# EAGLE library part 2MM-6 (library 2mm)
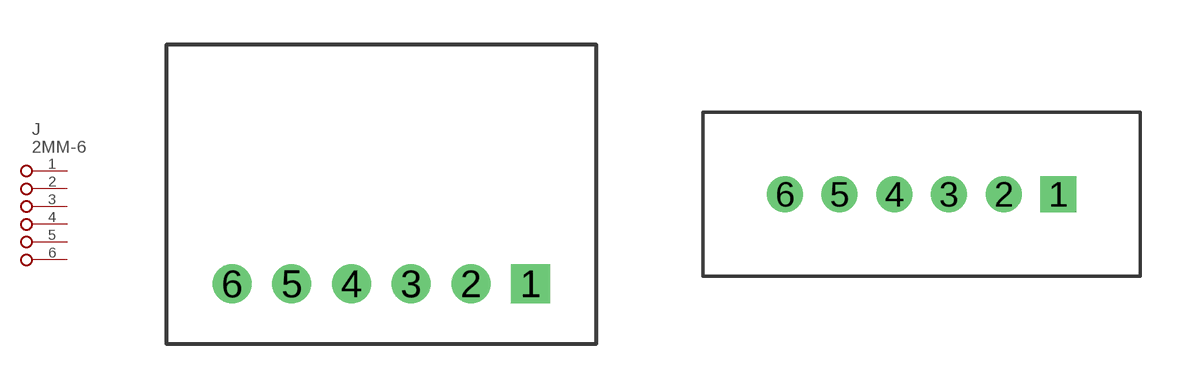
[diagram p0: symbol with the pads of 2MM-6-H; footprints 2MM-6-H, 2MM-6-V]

Designator prefix J

## 2MM-6H  [2MM-6-H]
1  1
2  2
3  3
4  4
5  5
6  6

## 2MM-6V  [2MM-6-V]
Pads as for 2MM-6-H

## Footprint 2MM-6-H (pad centres in mm)
drill 0.8 square: 1 0,0
drill 0.8 round: 2 -2,0; 3 -4,0; 4 -6,0; 5 -8,0; 6 -10,0

## Footprint 2MM-6-V (pad centres in mm)
drill 0.8 square: 1 0,0
drill 0.8 round: 2 -2,0; 3 -4,0; 4 -6,0; 5 -8,0; 6 -10,0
